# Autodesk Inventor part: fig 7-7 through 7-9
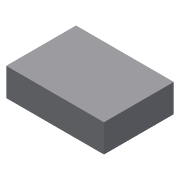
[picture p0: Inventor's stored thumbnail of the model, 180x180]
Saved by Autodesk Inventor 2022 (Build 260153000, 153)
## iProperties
Created: 2009-09
Part Number: fig 7-7 through 7-9
Document SubType Name: Modeling
Designer: Sham
Density: 1 g/cm^3
Material: Generic
Appearance: Default
Author: Sham
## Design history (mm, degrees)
sketch "Sketch1"
  geometry: L1 (-28, 20)-(0, 20); L2 (0, 20)-(0, 0); L3 (0, 0)-(-28, 0); L4 (-28, 0)-(-28, 20)
  constraints: 8 end point, 2 parallel, 1 horizontal, 1 perpendicular
extrude "Extrusion1" new body sketch "Sketch1" distance "d0" = 8; taper "d1" = 0 deg
body "Solid1"
